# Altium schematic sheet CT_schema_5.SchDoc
size 371 x 336 mm
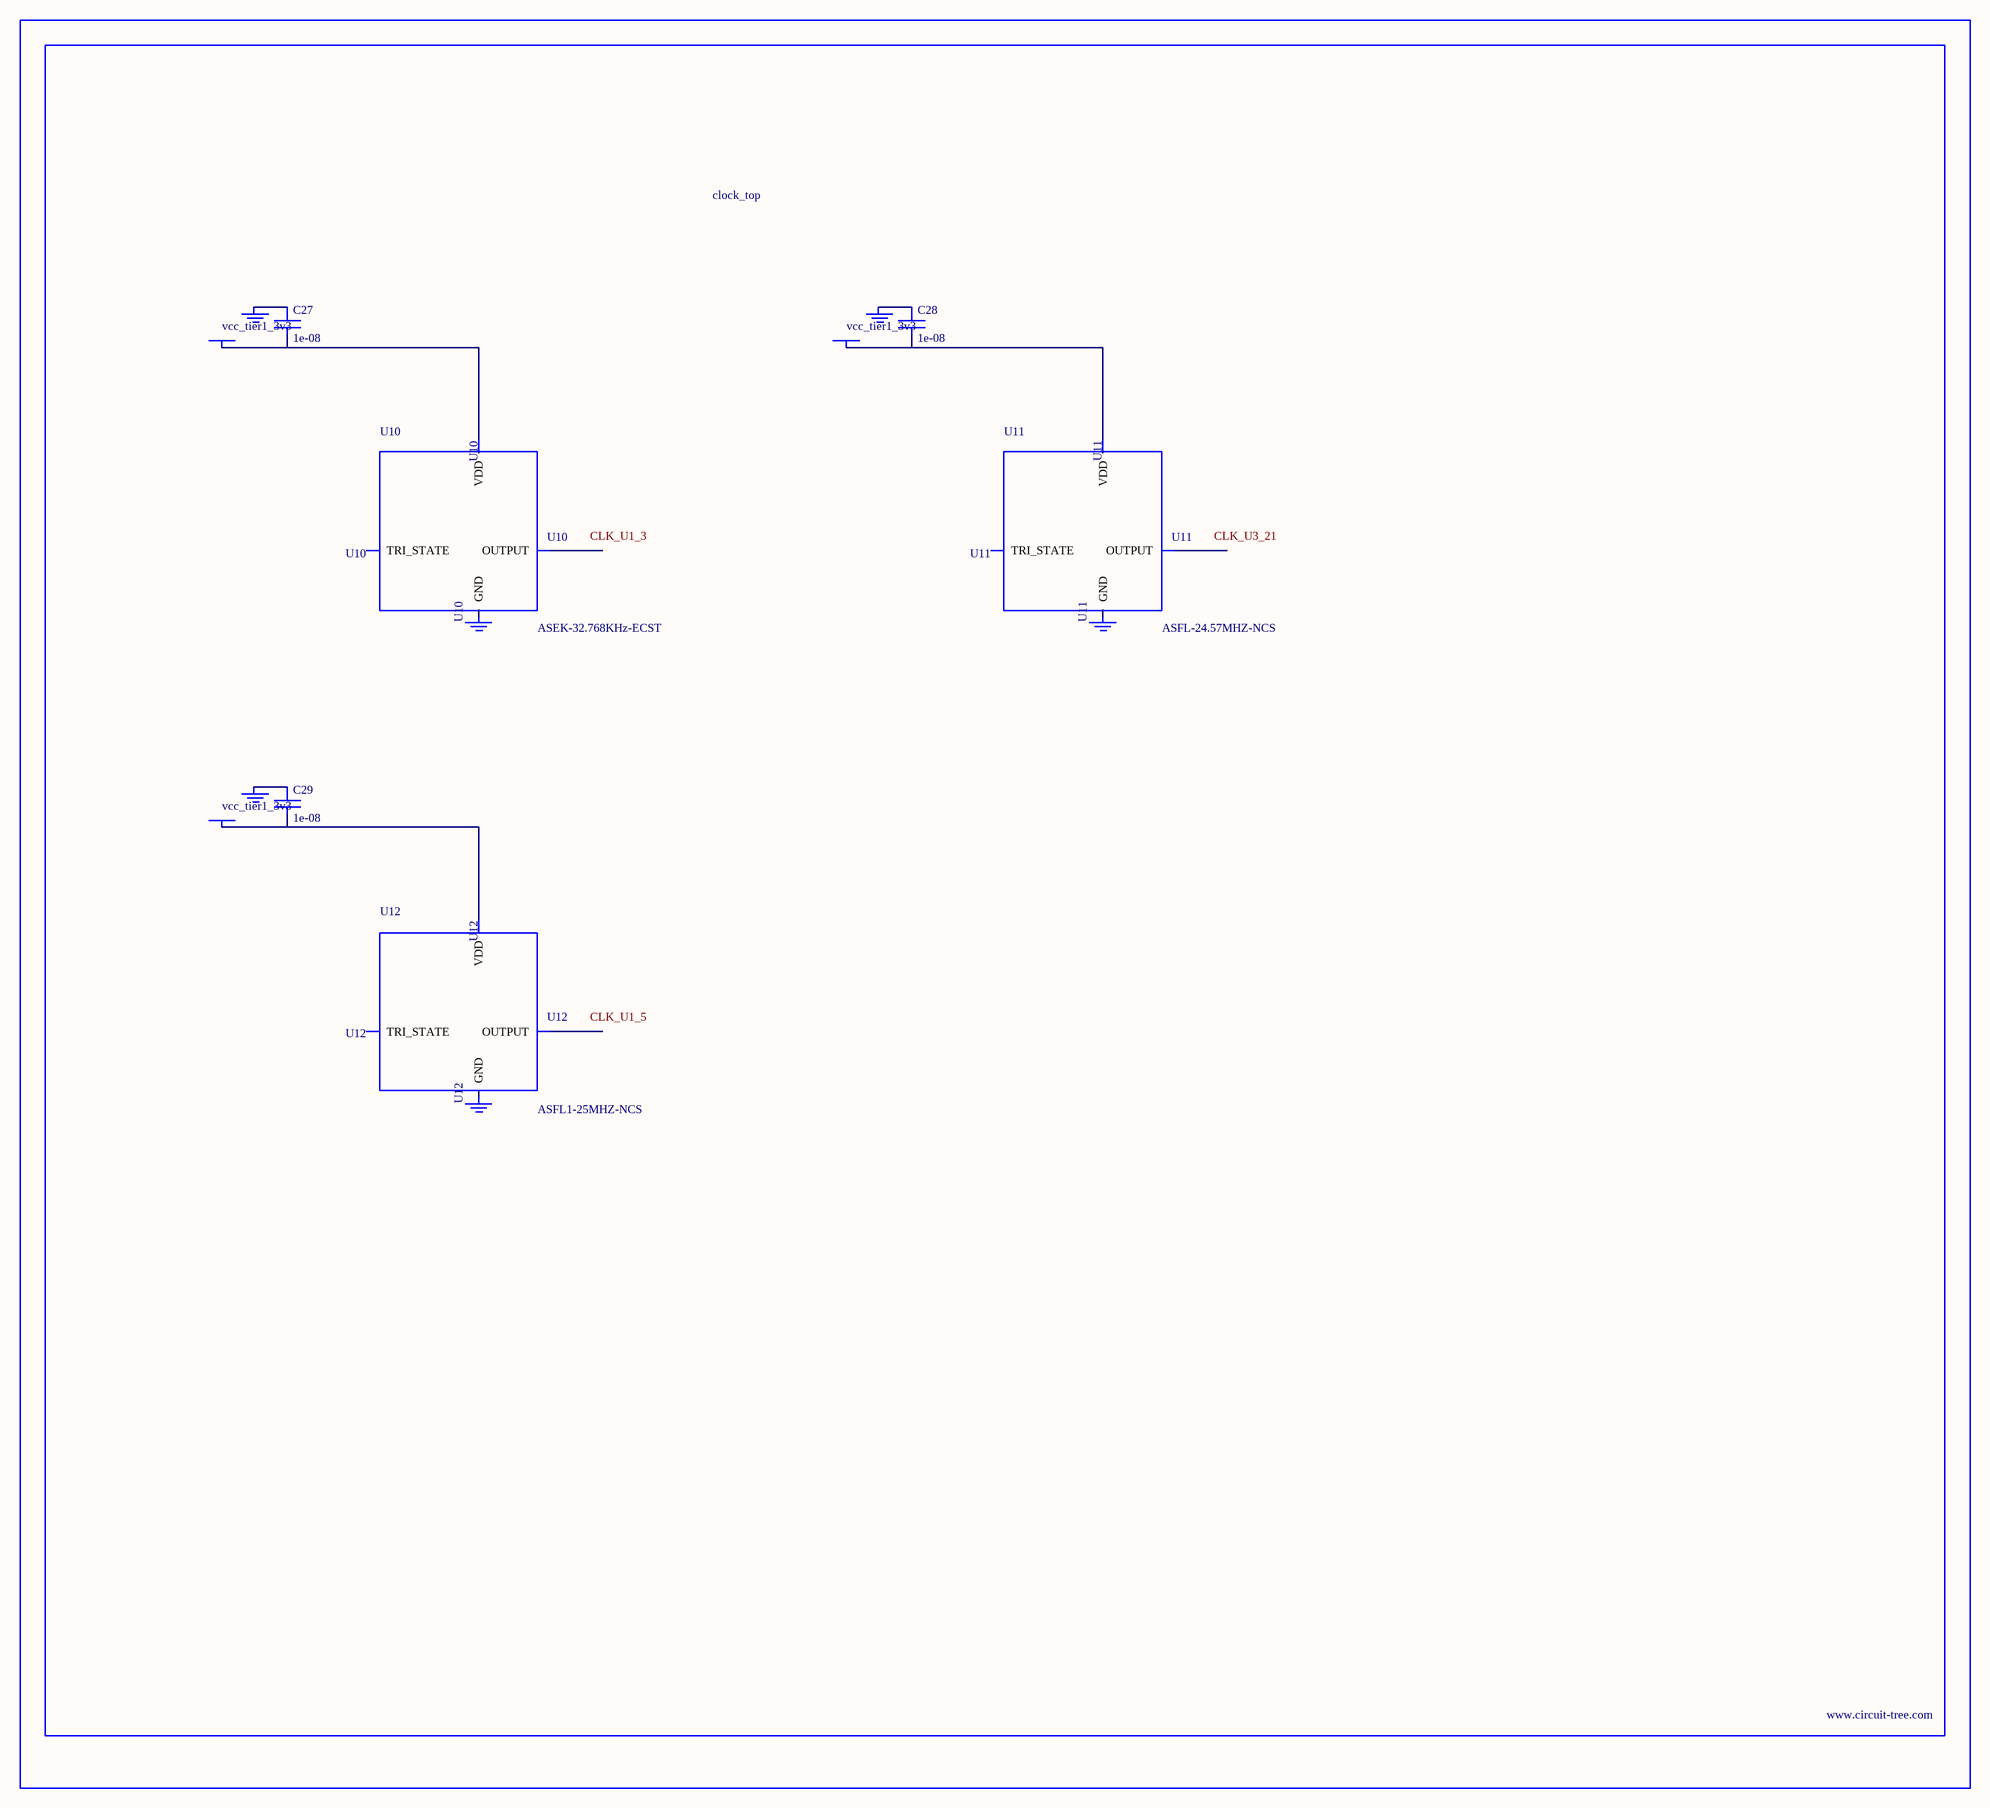
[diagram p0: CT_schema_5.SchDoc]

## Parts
BORDER4  (no value)
C27  1e-08  [C0402]
C28  1e-08  [C0402]
C29  1e-08  [C0402]
GND_INSTANCE_4_0  (no value)
GND_INSTANCE_4_1  (no value)
GND_INSTANCE_4_2  (no value)
GND_INSTANCE_4_3  (no value)
GND_INSTANCE_4_4  (no value)
GND_INSTANCE_4_5  (no value)
POWER_INSTANCE_4_0  vcc_tier1_3v3
POWER_INSTANCE_4_1  vcc_tier1_3v3
POWER_INSTANCE_4_2  vcc_tier1_3v3
U10  ASEK-32.768KHz-ECST  [ASEK]
U11  ASFL-24.57MHZ-NCS  [ASFL1]
U12  ASFL1-25MHZ-NCS  [ASFL1]

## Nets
NetC27_1: C27.1 GND_INSTANCE_4_0.0(GND)
NetC27_2: C27.2 POWER_INSTANCE_4_0.0(PWR) U10.4(VDD)
NetC28_1: C28.1 GND_INSTANCE_4_2.0(GND)
NetC28_2: C28.2 POWER_INSTANCE_4_1.0(PWR) U11.4(VDD)
NetC29_1: C29.1 GND_INSTANCE_4_4.0(GND)
NetC29_2: C29.2 POWER_INSTANCE_4_2.0(PWR) U12.4(VDD)

Not connected (* = marked no-connect by the designer): GND_INSTANCE_4_1 0(GND); GND_INSTANCE_4_3 0(GND); GND_INSTANCE_4_5 0(GND); U10 1(TRI_STATE) 2(GND) 3(OUTPUT); U11 1(TRI_STATE) 2(GND) 3(OUTPUT); U12 1(TRI_STATE) 2(GND) 3(OUTPUT)

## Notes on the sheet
- Labels drawn without touching a wire or pin: CLK_U1_3, CLK_U1_5, CLK_U3_21

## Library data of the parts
BORDER4 = BORDER_PAGE4
C27-C29 = C0402C103K3RAC
GND_INSTANCE_4_0-GND_INSTANCE_4_5 = GND
POWER_INSTANCE_4_0-POWER_INSTANCE_4_2 = PWR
